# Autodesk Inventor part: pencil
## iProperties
Shininess: 64.0
Length Units: 11272
Angle Units: 11279
Time Units: 11290
Mass Units: 11286
Length Display Precision: 3
Angle Display Precision: 2
Compacted: True
Part Number: pencil
Document SubType Name: Modeling
Created: 2004-01
Designer: Charles Bliss
Manufacturer: Standard
Standards Organization: Custom
Density: 0.0
Volumn: 0.0
Area: 0.0
PropertySet Name: Model Information
Control State: 0
Master: False
Checked Out: False
Author: Charles Bliss
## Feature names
1. Revolution1
2. Extrusion1
3. Split1
4. Fillet1
5. Fillet2
